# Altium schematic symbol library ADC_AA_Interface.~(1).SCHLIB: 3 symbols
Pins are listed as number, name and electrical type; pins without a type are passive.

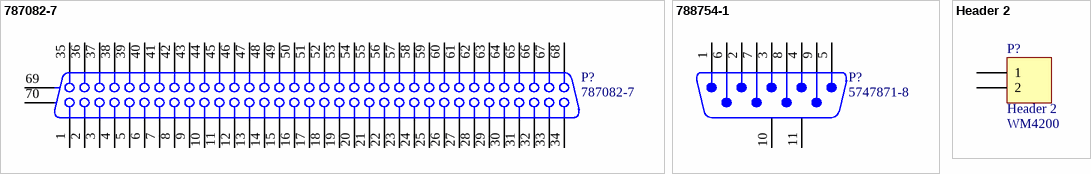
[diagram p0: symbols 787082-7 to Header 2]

## 787082-7
designator P?
Receptacle Assembly, Shielded, Right Angle, AMPLIMITE; Positions: 68; Note: Series III; Gender: Receptacle Header; Note: With Mating Lock; PCB_Layout: Complies with manufacturer's recommendation.; DrillSize: Corresponds to nominal value.
footprint 787082-7 (Connector; D Subminiature 050 Series; 68 Position; Right Angle)
signal-integrity model D Subminiature
pins: 1, 2, 3, 4, 5, 6, 7, 8, 9, 10, 11, 12, 13, 14, 15, 16, 17, 18, 19, 20, 21, 22, 23, 24, 25, 26, 27, 28, 29, 30, 31, 32, 33, 34, 35, 36, 37, 38, 39, 40, 41, 42, 43, 44, 45, 46, 47, 48, 49, 50, 51, 52, 53, 54, 55, 56, 57, 58, 59, 60, 61, 62, 63, 64, 65, 66, 67, 68, 69 MH1, 70 MH2

## 788754-1
designator P?, comment 5747871-8
Plug Assembly, Size 1, 9 Position, Right Angle, 8.08mm Series, Amplimite; Positions: 9; MatingConnector: 4-40 Threaded Insert; PCB_Layout: Complies with manufacturer's recommendation.; DrillSize: Corresponds to nominal value.
footprint 788754-1 (Connector; D Subminiature AMPLIMITE 2000; 9 Position; Right Angle)
signal-integrity model D Subminiature
footprint DB9/M
pins: 1, 2, 3, 4, 5, 6, 7, 8, 9, 10 MH1, 11 MH2

## Header 2
designator P?  Part Number: WM4200
Header, 2-Pin
footprint HDR1X2 (Connector; Header; 2 Position)
signal-integrity model Connector
pins: 1, 2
